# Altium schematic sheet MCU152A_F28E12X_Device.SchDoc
size 431 x 279 mm; Date: Not shown in title block; ApprovedBy: Not shown in title block; CheckedBy: Not shown in title block; Author: Not shown in title block; CompanyName: Not shown in title block; Engineer: Not shown in title block; Organization: Not shown in title block; Address1: Not shown in title block; Address2: Not shown in title block; Address3: Not shown in title block; Address4: Not shown in title block; DocumentNumber: 4; Revision: Use project parameter SCH_Rev; SheetNumber: 4; SheetTotal: 8; PageSetup: Record=PageOptions¦CenterHorizontal=True¦CenterVertical=True¦PrintScale=1.00¦XCorrection=1.00¦YCorrection=1.00¦PrintKind=0¦BorderSize=5000000¦LeftOffset=0¦BottomOffset=0¦Orientation=2¦PaperLength=1000¦PaperWidth=1000¦Scale=100¦PaperSource=15¦PrintQuality=600¦MediaType=1¦DitherType=10¦PaperKind=Letter¦PrintScaleMode=1; Orderable: LAUNCHXL-F2800157
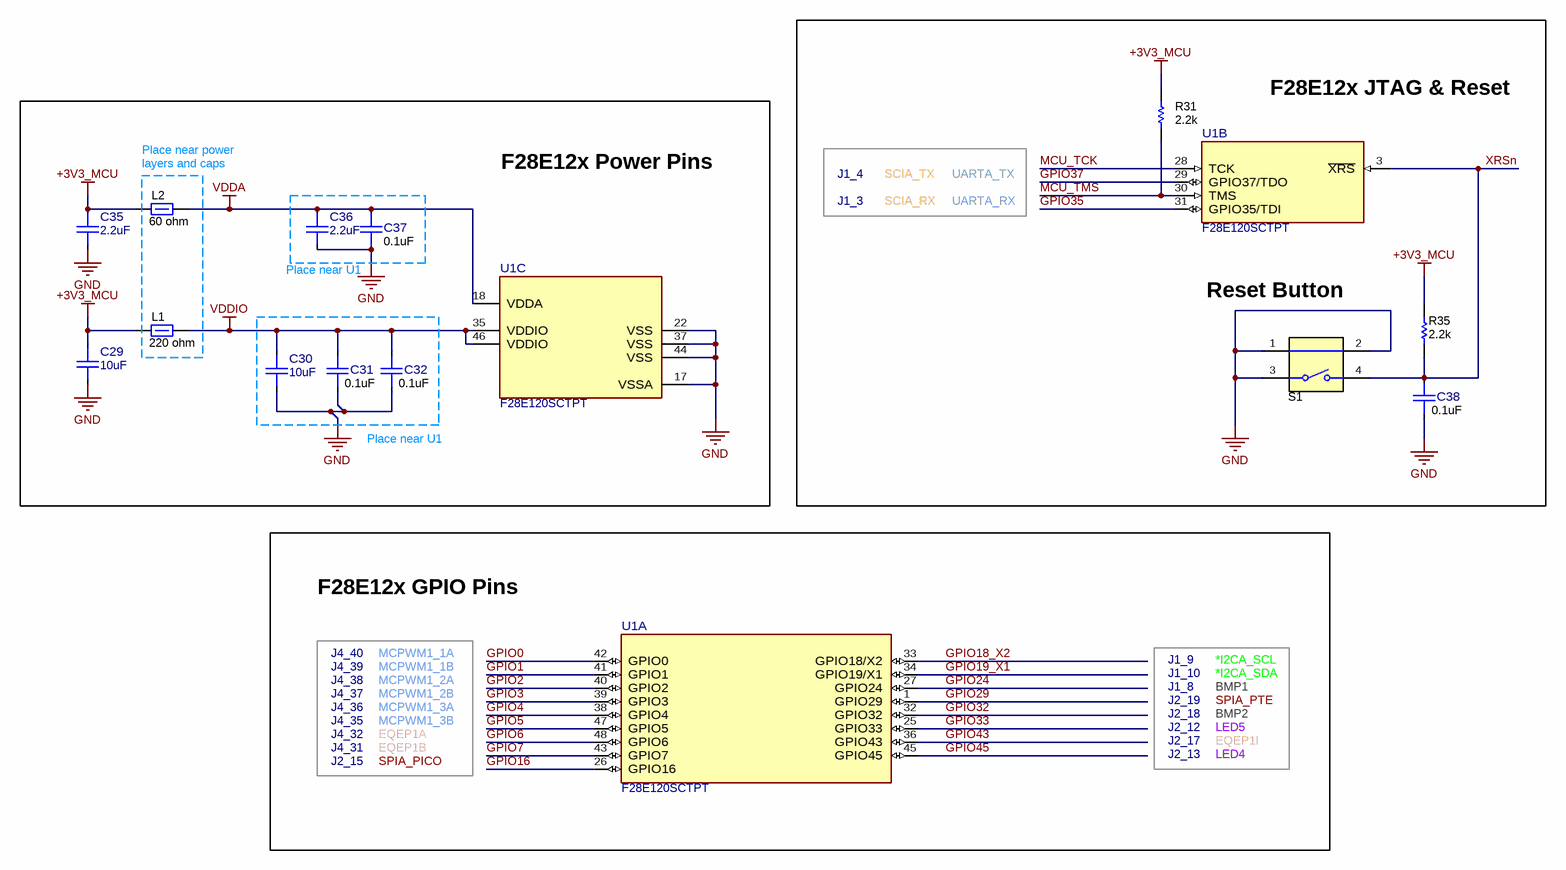
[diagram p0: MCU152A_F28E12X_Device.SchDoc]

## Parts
C29  ValueDisplayed: 10uF  [FP-885012106031_0603-MFG]  (hidden comment: 885012106031)
C30  ValueDisplayed: 10uF  [FP-885012106031_0603-MFG]  (hidden comment: 885012106031)
C31  ValueDisplayed: 0.1uF  [FP-885012205018_0402-MFG]  (hidden comment: 885012205018)
C32  ValueDisplayed: 0.1uF  [FP-885012205018_0402-MFG]  (hidden comment: 885012205018)
C35  ValueDisplayed: 2.2uF  [FP-885012106011_0603-MFG]  (hidden comment: 885012106011)
C36  ValueDisplayed: 2.2uF  [FP-885012106011_0603-MFG]  (hidden comment: 885012106011)
C37  ValueDisplayed: 0.1uF  [FP-885012205018_0402-MFG]  (hidden comment: 885012205018)
C38  ValueDisplayed: 0.1uF  [FP-885012205018_0402-MFG]  (hidden comment: 885012205018)
L1  ValueDisplayed: 220 ohm  [0805_HV]  (hidden comment: 742792022)
L2  value 60 ohm  [0805_HV]  (hidden comment: 742792063)
R31  ValueDisplayed: 2.2k  [0402]  (hidden comment: CRCW04022K20JNED)
R35  ValueDisplayed: 2.2k  [0402]  (hidden comment: CRCW04022K20JNED)
S1  1188E-1K2-V-TR  [SW_1188E]  (value not drawn)
U1  F28E120SCTPT  [PT0048A-MFG]  (parts A,B,C of 4)

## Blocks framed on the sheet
F28E12x Power Pins: C29-C32 C35-C37 L1 L2 U1
F28E12x GPIO Pins: U1

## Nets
+3V3_MCU: C29.1 C35.1 L1.1 L2.1 R31.2 R35.2
GND: C29.2 C30.2 C31.1 C32.1 C35.2 C36.2 C37.1 C38.1 S1.1 S1.2 S1.3 U1.17(VSSA) U1.22(VSS) U1.37(VSS) U1.44(VSS)
VDDA: C36.1 C37.2 L2.2 U1.18(VDDA)
VDDIO: C30.1 C31.2 C32.2 L1.2 U1.35(VDDIO) U1.46(VDDIO)
GPIO0: U1.42(GPIO0)
GPIO1: U1.41(GPIO1)
GPIO2: U1.40(GPIO2)
GPIO3: U1.39(GPIO3)
GPIO4: U1.38(GPIO4)
GPIO5: U1.47(GPIO5)
GPIO6: U1.48(GPIO6)
GPIO7: U1.43(GPIO7)
GPIO16: U1.26(GPIO16)
GPIO18_X2: U1.33(GPIO18/X2)
GPIO19_X1: U1.34(GPIO19/X1)
GPIO24: U1.27(GPIO24)
GPIO29: U1.1(GPIO29)
GPIO32: U1.32(GPIO32)
GPIO33: U1.25(GPIO33)
GPIO35: U1.31(GPIO35/TDI)
GPIO37: U1.29(GPIO37/TDO)
GPIO43: U1.36(GPIO43)
GPIO45: U1.45(GPIO45)
MCU_TCK: U1.28(TCK)
MCU_TMS: R31.1 U1.30(TMS)
XRSn: C38.2 R35.1 S1.4 U1.3(~{XRS})

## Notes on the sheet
- F28E12x JTAG & Reset
- (near L2) layers and caps
- Place near power
- J1_4
- J1_3
- SCIA_RX
- SCIA_TX
- UARTA_TX
- UARTA_RX
- Place near U1
- Reset Button
- J4_40
- J4_39
- J4_38
- J4_37
- MCPWM1_1A
- MCPWM1_1B
- MCPWM1_2A
- MCPWM1_2B
- J1_9
- J1_10
- J1_8
- J2_19
- *I2CA_SCL
- *I2CA_SDA
- SPIA_PTE
- BMP1
- J4_36
- J4_35
- J4_32
- J4_31
- J2_15
- SPIA_PICO
- EQEP1A
- EQEP1B
- MCPWM1_3A
- MCPWM1_3B
- J2_18
- J2_12
- J2_17
- J2_13
- BMP2
- LED5
- EQEP1I
- LED4

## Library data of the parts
C29 C30 = CMP-0124926-1: 10 µF ±20% 25V Ceramic Capacitor X5R 0603 (1608 Metric); Manufacturer: Wurth; AEC Qualified: No; Cap_F: 10µF; SizeZ_mm: 1mm; TempCo: 15%; Value: 10µF
C31 C32 C37 C38 = CMP-0090362-1: 0.1µF ±10% 10V Ceramic Capacitor X7R 0402 (1005 Metric); Manufacturer: Wurth Electronics; AEC Qualified: No; Value: 100nF; SizeZ_mm: 0.55mm; TempCo: 15%
C35 C36 = CMP-0124925-1: 2.2 µF ±20% 10V Ceramic Capacitor X5R 0603 (1608 Metric); Manufacturer: Wurth Electronics; AEC Qualified: No; Cap_F: 2.2µF; SizeZ_mm: 0.87mm; TempCo: 15%; Value: 2.2µF
L1 = CMP-0003073-1: Ferrite Bead, 220 ohm @ 100 MHz, 2 A, 0805; Manufacturer: Wurth Elektronik; Ztyp@1GHz_Ohm: 190.289; ZTyp@100MHz_Ohm: 220; SizeAreaWB_mm2: 6.75; DCR_ohm: 0.05; Value1: 0.05 ohm; Value: 220 ohm; Imax_A: 2A; SizeZ_mm: 1.45; SizeX_mm: 2; SizeY_mm: 1.25; SizeArea_mm2: 2.5
L2 = CMP-0003093-1: Ferrite Bead, 60 ohm @ 100 MHz, 3 A, 0805; Manufacturer: Wurth Elektronik; Ztyp@1GHz_Ohm: 95.384; ZTyp@100MHz_Ohm: 60; SizeAreaWB_mm2: 6.75; DCR_ohm: 0.025; Value1: 0.025 ohm; Imax_A: 3A; SizeZ_mm: 1.45; SizeX_mm: 2; SizeY_mm: 1.25; SizeArea_mm2: 2.5
R31 R35 = CMP-0026890-5: RES, 2.2 k, 5%, 0.063 W, AEC-Q200 Grade 0, 0402; Manufacturer: Vishay-Dale; Value: 2.2k; Value_Code: 2k20; Power_W: 63mW; Value2: 0.063W; VDC_V: 50V; TempCo: 200 ppm/C; EIA_Code: E24; AEC Category: Q200; AEC Qualified: Y; AEC Grade: 0; SizeArea_mm2: 0.5; SizeX_mm: 1; SizeZ_mm: 0.6
S1 = CMP-0002328-1: Switch, SPST, 0.05 A, 12 VDC, SMD; Manufacturer: Diptronics; SizeAreaWB_mm2: 53.9; SizeArea_mm2: 27.3; SizeX_mm: 7.8; SizeY_mm: 3.5; VDC_V: 12V; PositionCount: 1; CurrentRating_mA: 50A
U1 = CMP-0125361-1: F28E12x Real-Time Microcontrollers; Manufacturer: Texas Instruments; SizeZ_mm: 1.6mm; Core Architecture: C28x; Data Bus Width: 32bits; Frequency_Fixed: 160MHz; Interface: I2C,SPI,UART,SCI; Max Supply Voltage: 3.63V; Memory Size: 128KBytes; Memory Type: FLASH; Min Supply Voltage: 2.8V; Number Of A/D Converters: 1; Number Of Adc Channels: 9; Number Of I/Os: 27; Number Of Pwm Channels: 8; Number Of Timers/Counters: 4; Number Of Uart Channels: 2; Ram Size: 16KBytes; Standoff Height: 0.05mm; TJmax_C: +125°C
